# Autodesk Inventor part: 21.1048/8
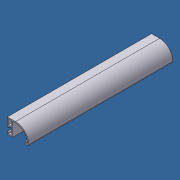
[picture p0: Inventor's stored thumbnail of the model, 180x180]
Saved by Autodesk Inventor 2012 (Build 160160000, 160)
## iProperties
Created: 2007-02
Part Number: 21.1048/8
Material: Aluminum-6061
Document SubType Name: Modeling
Designer: Andy Moles
Density: 2.71 g/cm^3
Mass: 273.197 g
Surface Area: 814.502 cm^2
Volume: 100.811 cm^3
Description: L = 12", MILL TO 21.1048/8
Vendor: F
Stock Number: 20.1045 HANDLE PROFILE
Author: Andy Moles
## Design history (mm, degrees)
sketch "Sketch1"
  geometry: L1 (-20, 20)-(-14, 20) reference; L2 (-14, 9.5)-(-20, 9.5) reference; L3 (-11.5, -9.5)-(-22.5, -9.5) reference; L4 (-11.5, 20)-(-11.5, -9.5) reference; L5 (-5.5, 20)-(-11.5, 20) reference; L6 (-22.5, 22.5)-(-5.5, 22.5) reference; L7 (-22.5, 4.75)-(-22.5, 22.5) reference; L8 (-20, 4.25)-(-22.5, 4.25) reference; L9 (-20, 6.5)-(-20, 4.75) reference; L10 (-14, 7)-(-20, 7) reference; L11 (-14, 0.5)-(-14, 6.5) reference; L12 (-13.5, 0)-(-14, 0.5) reference; L13 (-14, -0.5)-(-13.5, 0) reference; L14 (-14, -7)-(-14, -0.5) reference; L15 (-20, -7)-(-14, -7) reference; L16 (-22.5, -4.25)-(-20, -4.25) reference; L17 (-14, 20)-(-14, 9.5) reference; L18 (-14, 7)-(-14, 6.5) reference; L19 (-20, 6.5)-(-20, 7) reference; L20 (-20, 9.5)-(-20, 20) reference; L21 (-22.5, -9.5)-(-22.5, -4.25) reference; L22 (-22.5, 4.25)-(-22.5, 4.75) reference; L23 (-20, 4.75)-(-20, 4.25) reference; L24 (-20, -4.25)-(-20, -7) reference; A1 r 25.5 centre (-5.5, -5.5) between (20, -5.5) and (-5.5, 20) reference; A2 r 1.5 centre (18.5, -5.5) between (17.241, -4.684) and (20, -5.5) reference; A3 r 1.25 centre (16.193, -4.004) between (17.241, -4.684) and (15.144, -3.324) reference; A4 r 4 centre (18.5, -5.5) between (15.144, -3.324) and (22.5, -5.5) reference; A5 r 28 centre (-5.5, -5.5) between (22.5, -5.5) and (-5.5, 22.5) reference
  constraints: 48 end point, 13 vertical, 10 point on circle, 9 horizontal, 5 centre point, 41 other
extrude "Extrusion1" new body sketch "Sketch1" stored distance "d0" = 304.8; taper "d1" = 0 deg
sketch "Sketch2"
  geometry: L1 (0, 0)-(0, 29.5) reference; L2 (-304.8, 29.5)-(-304.8, 0) reference; L3 (-304.8, 9.5)-(0, 9.5) reference; 3 further points
  constraints: 2 point on line
  dimensions: "d2" = 38.1 distance from line of point (-266.7, 9.5) L2; "d3" = 38.1 distance from line of point (-38.1, 9.5) L1 (= d2)
hole "Hole1" sketch "Sketch2" at (-38.1, 9.5), (-266.7, 9.5) diameter "d4" = 8; stored, may be unused: countersink angle "d8" = 90 deg, drill point angle "d10" = 118 deg; dims "d5" = 6, "d6" = 4, "d7" = 2, "d9" = 8
body "Solid1"
